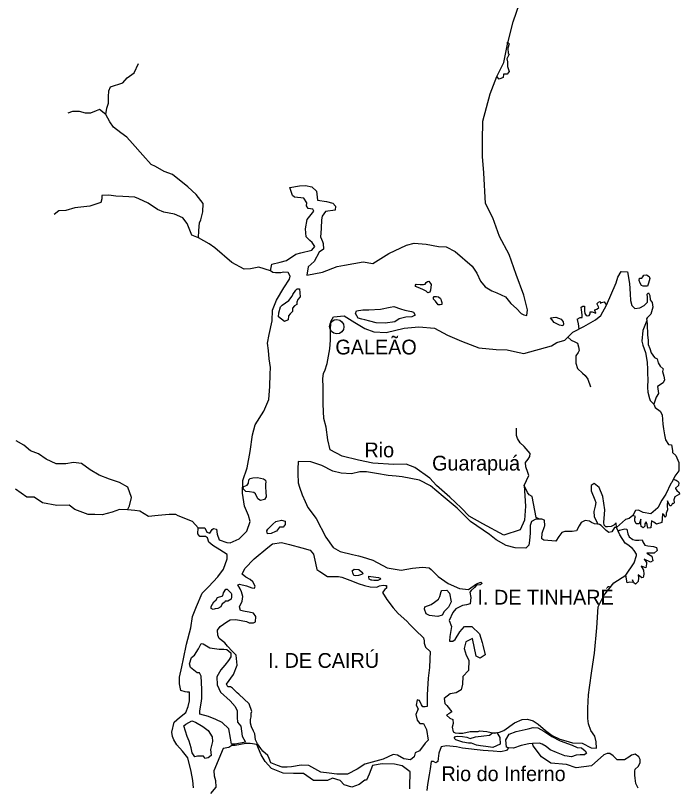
# Model space of a CAD drawing. Extents: x 662444 to 1640468, y 7452018 to 9606170.
# Drawn here: x 1132606 to 1162596, y 8490043 to 8524923 of the extents above; entities that cross this region are included whole.
import ezdxf

# ---------------------------------------------------------------- set-up
doc = ezdxf.new("R2010")
doc.units = 0
for name, color, linetype in [('Level 1', 7, 'Continuous'), ('Level 2', 7, 'Continuous'), ('Level 3', 7, 'Continuous')]:
    doc.layers.add(name, color=color, linetype=linetype)

msp = doc.modelspace()

# ---------------------------------------------------------------- linework, layer by layer
at = {"layer": 'Level 1'}
for points in [[(1153711, 8520144), (1154046, 8521381), (1154349, 8522164), (1154658, 8522801), (1154831, 8523631), (1155084, 8524637), (1155365, 8525464)], [(1154831, 8523631), (1154833, 8523709), (1154896, 8523641), (1154848, 8523442), (1154853, 8523208), (1154896, 8523173), (1154793, 8522965), (1154822, 8522830), (1154831, 8522730), (1154828, 8522619), (1154899, 8522395), (1154809, 8522275), (1154645, 8522268), (1154631, 8522123), (1154454, 8522039), (1154349, 8522164)], [(1136687, 8520441), (1136737, 8520729), (1136808, 8520961), (1136815, 8521239), (1136821, 8521517), (1136902, 8521693), (1137450, 8521880), (1137652, 8522097), (1137973, 8522334), (1138168, 8522752)], [(1140877, 8514871), (1140885, 8515205), (1140915, 8515549), (1140972, 8515692), (1141068, 8516057), (1141077, 8516423), (1140771, 8516831), (1140387, 8517174), (1139693, 8517735), (1139326, 8517877), (1138929, 8518098), (1138735, 8518191), (1138364, 8518612), (1137897, 8519134), (1137632, 8519418), (1137364, 8519625), (1137033, 8519877), (1136875, 8520114), (1136687, 8520441), (1136398, 8520670), (1136256, 8520618), (1135992, 8520513), (1135763, 8520508), (1135503, 8520580), (1135188, 8520588), (1134968, 8520504)], [(1143308, 8505974), (1143438, 8506426), (1143824, 8507051), (1144043, 8507579), (1144090, 8508167), (1144114, 8508712), (1144122, 8509023), (1144066, 8509413), (1144031, 8509792), (1143985, 8510116), (1144070, 8510503), (1144205, 8511133), (1144217, 8511611), (1144402, 8512063), (1144731, 8512622), (1144980, 8513016), (1145015, 8513138), (1144922, 8513307), (1144715, 8513323), (1144584, 8513293), (1144344, 8513298), (1144225, 8513312), (1144129, 8513381), (1144190, 8513680), (1144563, 8513771), (1144848, 8513853), (1145268, 8514143), (1145498, 8514205), (1145991, 8514315), (1146126, 8514478), (1146000, 8514671), (1145893, 8514751), (1145734, 8514922), (1145710, 8515289), (1145774, 8515710), (1146077, 8516081), (1146036, 8516171), (1145830, 8516209), (1145745, 8516322), (1145770, 8516455), (1145634, 8516670), (1145200, 8516714), (1145114, 8516793), (1145003, 8517152), (1145430, 8517220), (1145702, 8517235), (1145984, 8517173), (1146197, 8516979), (1146252, 8516577), (1146654, 8516512), (1146946, 8516438), (1147052, 8516302), (1147047, 8516124), (1146610, 8516068), (1146464, 8515860), (1146427, 8515683), (1146407, 8515306), (1146402, 8515083), (1146387, 8514928), (1146469, 8514715), (1146499, 8514614), (1146515, 8514358), (1146316, 8514229), (1146099, 8513812), (1145831, 8513563), (1145768, 8513186), (1146479, 8513325), (1147128, 8513587), (1147466, 8513645), (1148308, 8513792), (1148742, 8513715), (1149472, 8514164), (1150265, 8514545), (1150604, 8514637), (1151148, 8514590), (1151712, 8514488), (1152059, 8514468), (1152468, 8514258), (1153225, 8513595), (1153435, 8513278), (1153600, 8512918), (1153812, 8512657), (1154123, 8512483), (1154350, 8512388), (1154737, 8512212), (1154981, 8511917), (1155236, 8511688), (1155449, 8511460), (1155567, 8511391), (1155697, 8511365), (1155736, 8511631), (1155567, 8512281), (1155219, 8513223), (1154904, 8514121), (1154467, 8514943), (1154160, 8515774), (1153828, 8516427), (1153753, 8517819), (1153694, 8518554), (1153701, 8519255), (1153711, 8520144)], [(1144129, 8513381), (1143599, 8513550), (1143227, 8513470), (1142933, 8513455), (1142385, 8513768), (1141617, 8514420), (1141349, 8514604), (1140877, 8514871), (1140564, 8515001), (1140359, 8515529), (1140169, 8515778), (1139792, 8515943), (1139304, 8516043), (1139024, 8516150), (1138606, 8516449), (1138175, 8516637), (1138003, 8516708), (1137459, 8516743), (1137133, 8516762), (1136829, 8516802), (1136513, 8516788), (1136509, 8516632), (1136462, 8516466), (1135968, 8516311), (1135281, 8516239), (1134875, 8516115), (1134570, 8516100), (1134348, 8515938)], [(1156265, 8502165), (1156125, 8502235), (1155942, 8503196), (1155802, 8503266), (1155729, 8503379), (1155584, 8503694), (1155637, 8502759), (1155600, 8502115), (1155393, 8501686), (1154658, 8501437), (1153713, 8501950), (1153101, 8502299), (1152729, 8502675), (1152218, 8503154), (1151622, 8503692), (1151314, 8504022), (1150640, 8504494), (1150252, 8504659), (1149697, 8504640), (1148751, 8504696), (1148091, 8504834), (1147366, 8505019), (1146818, 8505299), (1146709, 8505758), (1146636, 8506327), (1146537, 8506718), (1146509, 8507364), (1146495, 8508131), (1146482, 8508510), (1146510, 8508765), (1146578, 8508863), (1146684, 8509194), (1146798, 8509859), (1146829, 8510258), (1146839, 8510647), (1146849, 8511092), (1146974, 8511311), (1147444, 8511355), (1147937, 8511054), (1148377, 8510788), (1148787, 8510633), (1149341, 8510598), (1150163, 8510789), (1150817, 8510851), (1151524, 8510800), (1152115, 8510486), (1152750, 8510214), (1153527, 8509906), (1154320, 8509831), (1154809, 8509819), (1155145, 8509744), (1155567, 8509645), (1156817, 8509992), (1157060, 8510153), (1157422, 8510255), (1157769, 8510614), (1158276, 8510868), (1158806, 8511167), (1159039, 8511361), (1159301, 8511833), (1159729, 8512846), (1159812, 8513099), (1159960, 8513351), (1160242, 8513333), (1160338, 8512819), (1160370, 8512340), (1160385, 8512051), (1160434, 8511827), (1160572, 8511679), (1160801, 8511707), (1161000, 8511813), (1161145, 8511976), (1161148, 8512076), (1161151, 8512199), (1161132, 8512333), (1161188, 8512387), (1161261, 8512274), (1161267, 8512073), (1161362, 8511949), (1161390, 8511748), (1161295, 8511428), (1161128, 8511265), (1161104, 8511210), (1161114, 8511143), (1161123, 8511098), (1161132, 8510987), (1161152, 8510486), (1161179, 8510252), (1161174, 8510051), (1161256, 8509871), (1161317, 8509681), (1161464, 8509477), (1161582, 8509407), (1161632, 8509228), (1161727, 8509081), (1161854, 8508956), (1161830, 8508834), (1161879, 8508633), (1161918, 8508465), (1161850, 8508322), (1161595, 8508161)], [(1161199, 8512831), (1161152, 8512688), (1160945, 8512693), (1160881, 8512728), (1160818, 8512830), (1160777, 8512953), (1160780, 8513053), (1160899, 8513050), (1160934, 8513116), (1160990, 8513193), (1161099, 8513201), (1161217, 8513131), (1161248, 8513042), (1161199, 8512831)], [(1145103, 8512246), (1145137, 8512312), (1145272, 8512509), (1145328, 8512574), (1145437, 8512571), (1145455, 8512393), (1145461, 8512215), (1145360, 8512095), (1145314, 8511963), (1145311, 8511863), (1145212, 8511810), (1145122, 8511701), (1145119, 8511556), (1145018, 8511436), (1144940, 8511360), (1144914, 8511172), (1144749, 8511098), (1144492, 8511304), (1144497, 8511482), (1144579, 8511758), (1144647, 8511834), (1144945, 8512038), (1145103, 8512246)], [(1151348, 8512517), (1151324, 8512429), (1151236, 8512397), (1151151, 8512466), (1151000, 8512537), (1150795, 8512631), (1150677, 8512678), (1150667, 8512745), (1150701, 8512789), (1150875, 8512773), (1151038, 8512769), (1151104, 8512779), (1151160, 8512866), (1151216, 8512910), (1151281, 8512919), (1151376, 8512772), (1151348, 8512517)], [(1151575, 8512011), (1151490, 8512113), (1151481, 8512180), (1151515, 8512224), (1151613, 8512233), (1151710, 8512208), (1151796, 8512139), (1151817, 8512105), (1151837, 8512049), (1151857, 8511960), (1151854, 8511860), (1151789, 8511850), (1151702, 8511852), (1151575, 8512011)], [(1158068, 8510764), (1158028, 8510986), (1157990, 8511187), (1157979, 8511209), (1158101, 8511284), (1158199, 8511271), (1158191, 8511404), (1158175, 8511627), (1158156, 8511750), (1158233, 8511792), (1158299, 8511791), (1158304, 8511557), (1158312, 8511457), (1158386, 8511366), (1158451, 8511353), (1158517, 8511374), (1158562, 8511440), (1158564, 8511528), (1158652, 8511537), (1158813, 8511478), (1158773, 8511601), (1158806, 8511634), (1158861, 8511655), (1158950, 8511730), (1158878, 8511877), (1158868, 8511910), (1158935, 8511975), (1159011, 8511996), (1159031, 8511906), (1159065, 8511961), (1159185, 8511991), (1159301, 8511833)], [(1149522, 8511750), (1149686, 8511779), (1149988, 8511672), (1150183, 8511611), (1150334, 8511574), (1150497, 8511548), (1150583, 8511513), (1150656, 8511377), (1150513, 8511314), (1150229, 8511299), (1149933, 8511217), (1149734, 8511077), (1149308, 8511021), (1148895, 8511042), (1148614, 8511116), (1148386, 8511166), (1148246, 8511202), (1148083, 8511251), (1147958, 8511465), (1148005, 8511586), (1148288, 8511624), (1148571, 8511617), (1149084, 8511660), (1149522, 8511750)], [(1156930, 8511057), (1156824, 8511182), (1156772, 8511261), (1157012, 8511289), (1157250, 8511205), (1157334, 8511081), (1157353, 8510980), (1157329, 8510903), (1157167, 8510929), (1156930, 8511057)], [(1161114, 8511143), (1160939, 8510691), (1160895, 8510214), (1160944, 8510024), (1161056, 8509698), (1161132, 8509263), (1161146, 8508929), (1161152, 8508740), (1161157, 8508495), (1161148, 8508117), (1161164, 8507905), (1161244, 8507614), (1161264, 8507524), (1161434, 8507365)], [(1157535, 8510397), (1157694, 8510249), (1157867, 8510178), (1157985, 8510119), (1158035, 8509951), (1158064, 8509784), (1158018, 8509696), (1157916, 8509542), (1157919, 8509220), (1157990, 8508973), (1158213, 8508757), (1158330, 8508654), (1158457, 8508495), (1158568, 8508147)], [(1161595, 8508161), (1161652, 8507837), (1161539, 8507673), (1161434, 8507365), (1161495, 8507207), (1161720, 8507046), (1161814, 8506888), (1161836, 8506454), (1161864, 8506253), (1161911, 8505973), (1161960, 8505750), (1162096, 8505546), (1162237, 8505520), (1162275, 8505275), (1162272, 8505186), (1162432, 8505048), (1162566, 8504723), (1162567, 8504344), (1162376, 8504116), (1162249, 8503818), (1162205, 8503775), (1161975, 8503302), (1161794, 8503018), (1161622, 8502677), (1161300, 8502407), (1160953, 8502471), (1160749, 8502577), (1160607, 8502558), (1160482, 8502339), (1160326, 8502198), (1160161, 8502157), (1159750, 8501790)], [(1140647, 8490027), (1140612, 8490361), (1140545, 8490763), (1140397, 8491389), (1140144, 8491685), (1139900, 8491968), (1139754, 8492205), (1139692, 8492352), (1139675, 8492541), (1139773, 8492994), (1140017, 8493200), (1140306, 8493437), (1140399, 8493702), (1140460, 8493967), (1140467, 8494245), (1140469, 8494345), (1140361, 8494359), (1140263, 8494361), (1140079, 8494421), (1140021, 8494723), (1140018, 8495034), (1140116, 8495499), (1140190, 8495853), (1140337, 8496517), (1140529, 8497257), (1140596, 8497767), (1140781, 8498218), (1141035, 8498823), (1141325, 8499117), (1141749, 8499562), (1142008, 8499912), (1142160, 8500375), (1142165, 8500564), (1141833, 8500783), (1141522, 8500980), (1141341, 8501129), (1141280, 8501319), (1141183, 8501377), (1141086, 8501380), (1141031, 8501381), (1140933, 8501383), (1140849, 8501508), (1140856, 8501774), (1141051, 8501769), (1141160, 8501778), (1141243, 8501587), (1141383, 8501528), (1141496, 8501703), (1141551, 8501746), (1141681, 8501721), (1141719, 8501487), (1141811, 8501229), (1142145, 8501109), (1142309, 8501105), (1142715, 8501284), (1142894, 8501458), (1143061, 8501632), (1143202, 8502062), (1143133, 8502331), (1142947, 8502747), (1142863, 8503349), (1142877, 8503916), (1143065, 8504489), (1143213, 8505220), (1143308, 8505974)], [(1155584, 8503694), (1155791, 8504134), (1155740, 8504280), (1155659, 8504538), (1155642, 8504727), (1155755, 8504880), (1155834, 8505001), (1155848, 8505134), (1155573, 8505452), (1155392, 8505612), (1155277, 8505815), (1155226, 8505950), (1155234, 8506283)], [(1137665, 8502596), (1137757, 8502772), (1137853, 8503147), (1137679, 8503607), (1137303, 8503828), (1136850, 8503972), (1136386, 8504150), (1135978, 8504393), (1135583, 8504680), (1135225, 8504733), (1134886, 8504664), (1134440, 8504674), (1133988, 8504874), (1133645, 8505116), (1133290, 8505258), (1132991, 8505509), (1132636, 8505707)], [(1150075, 8504074), (1149804, 8504114), (1149434, 8504134), (1148914, 8504225), (1148459, 8504303), (1148306, 8504307), (1148154, 8504299), (1147782, 8504219), (1147314, 8504242), (1146936, 8504340), (1146441, 8504585), (1145945, 8504753), (1145368, 8504778), (1145360, 8504423), (1145355, 8504234), (1145378, 8503811), (1145438, 8503620), (1145560, 8503261), (1145694, 8502958), (1145808, 8502699), (1146187, 8502201), (1146624, 8501356), (1146950, 8500892), (1147272, 8500707), (1147824, 8500571), (1148094, 8500509), (1148256, 8500471), (1148742, 8500315), (1149398, 8499965), (1150026, 8499861), (1150529, 8499949), (1150987, 8499993), (1151291, 8499963), (1151376, 8499894), (1151695, 8499575), (1152144, 8499264), (1152661, 8499029), (1153063, 8498986), (1153428, 8499243), (1153626, 8499316), (1153679, 8499260), (1153590, 8499206), (1153427, 8499188), (1153337, 8499079), (1153192, 8498938), (1153125, 8498862), (1153163, 8498627), (1153134, 8498339), (1152970, 8498298), (1152795, 8498269), (1152486, 8498110), (1152351, 8497947), (1152190, 8497595), (1152303, 8497325), (1152216, 8496871), (1152211, 8496660), (1152352, 8496657), (1152463, 8496732), (1152678, 8497082), (1152891, 8497322), (1153217, 8497314), (1153568, 8496982), (1153689, 8496601), (1153719, 8496478), (1153817, 8496042), (1153596, 8495892), (1153413, 8495985), (1153248, 8496779), (1152939, 8496620), (1152866, 8496321), (1152957, 8496030), (1153082, 8495804), (1153059, 8495327), (1152802, 8495055), (1152794, 8494711), (1152733, 8494456), (1152502, 8494329), (1152239, 8494279), (1151973, 8494064), (1152000, 8493841), (1152021, 8493807), (1152085, 8493749), (1152317, 8493466), (1152184, 8493369), (1152074, 8493316), (1152223, 8493179), (1152352, 8493120), (1152369, 8492931), (1152321, 8492765), (1152371, 8492564), (1152457, 8492517), (1152631, 8492502), (1152815, 8492497), (1153133, 8492578), (1153503, 8492580), (1153569, 8492601), (1153894, 8492570), (1154219, 8492507), (1154459, 8492545), (1154668, 8492618), (1155144, 8492962)], [(1143804, 8503993), (1143901, 8503936), (1143920, 8503835), (1143897, 8503769), (1143894, 8503680), (1143893, 8503613), (1143920, 8503401), (1143926, 8503179), (1143858, 8503058), (1143671, 8503007), (1143554, 8503088), (1143439, 8503313), (1143375, 8503370), (1143180, 8503408), (1143006, 8503412), (1142900, 8503515), (1142891, 8503604), (1142925, 8503637), (1143068, 8503700), (1143135, 8503798), (1143150, 8503943), (1143206, 8503997), (1143326, 8504038), (1143544, 8504055), (1143804, 8503993)], [(1155144, 8492962), (1155486, 8493120), (1155736, 8493136), (1155985, 8493063), (1156210, 8492913), (1156539, 8492616), (1156850, 8492397), (1157182, 8492222), (1157453, 8492148), (1157755, 8492063), (1158201, 8492041), (1158598, 8491830), (1158848, 8491824), (1158833, 8492103), (1158775, 8492360), (1158585, 8492620), (1158484, 8492923), (1158457, 8493169), (1158458, 8493625), (1158484, 8494225), (1158525, 8494557), (1158631, 8495322), (1158748, 8496109), (1158853, 8497252), (1158920, 8498207), (1159183, 8498723), (1159633, 8499290), (1160175, 8499632), (1160548, 8500190), (1160654, 8500521), (1160656, 8500588), (1160551, 8500746), (1160466, 8500837), (1160253, 8501010), (1160145, 8501079), (1159904, 8501452), (1159750, 8501790), (1159662, 8501792), (1159538, 8501595), (1159396, 8501565), (1159278, 8501657), (1159204, 8501725), (1159055, 8501874), (1158984, 8501929), (1158904, 8501944), (1158752, 8501959), (1158612, 8502018), (1158527, 8502076), (1158332, 8502114), (1158155, 8502018), (1158064, 8501865), (1157939, 8501645), (1157753, 8501617), (1157416, 8501603), (1157273, 8501562), (1157149, 8501387), (1157002, 8501179), (1156470, 8501215), (1156384, 8501272), (1156391, 8501539), (1156496, 8501837), (1156519, 8501870), (1156492, 8502115), (1156384, 8502162), (1156265, 8502165), (1156112, 8502169), (1155903, 8502063), (1155844, 8501886), (1155857, 8501541), (1155827, 8501197), (1155790, 8500998), (1155656, 8500857), (1155177, 8500869), (1154766, 8500979), (1154315, 8501235), (1154016, 8501475), (1153160, 8502064), (1152554, 8502657), (1151925, 8503195), (1151350, 8503676), (1150855, 8503922), (1150075, 8504074)], [(1162308, 8503973), (1162437, 8503936), (1162534, 8503867), (1162565, 8503811), (1162551, 8503689), (1162417, 8503570), (1162417, 8503547), (1162480, 8503457), (1162575, 8503365), (1162596, 8503298), (1162386, 8503181), (1162339, 8503038), (1162357, 8502904), (1162313, 8502860), (1162270, 8502884), (1162212, 8502763), (1162158, 8502775), (1162044, 8503000), (1162038, 8502767), (1162055, 8502589), (1161997, 8502445), (1161995, 8502334), (1161949, 8502235), (1161887, 8502381), (1161822, 8502405), (1161806, 8502183), (1161802, 8502017), (1161549, 8501934), (1161432, 8502037), (1161335, 8502095), (1161321, 8501940), (1161295, 8501773), (1161164, 8501754), (1161144, 8501822), (1161135, 8501922), (1161084, 8502046), (1161027, 8501958), (1161025, 8501858), (1160947, 8501782), (1160861, 8501840), (1160853, 8501962), (1160848, 8502174), (1160766, 8501953), (1160635, 8501957), (1160573, 8502092), (1160576, 8502214), (1160600, 8502291), (1160482, 8502339)], [(1140856, 8501774), (1140602, 8502069), (1139955, 8502319), (1139847, 8502377), (1139543, 8502373), (1139052, 8502340), (1138616, 8502295), (1138230, 8502527), (1138002, 8502566), (1137665, 8502596), (1137307, 8502605), (1136967, 8502490), (1136517, 8502357), (1136191, 8502376), (1135886, 8502372), (1135294, 8502608), (1135026, 8502793), (1134471, 8502784), (1133832, 8502910), (1133446, 8503164), (1133120, 8503161), (1132606, 8503517)], [(1159750, 8501790), (1159733, 8502001), (1159632, 8501893), (1159511, 8501840), (1159348, 8501822), (1159261, 8501824), (1159197, 8501892), (1159178, 8502015), (1159209, 8502392), (1159214, 8502593), (1159131, 8503184), (1158967, 8503600), (1158743, 8503772), (1158610, 8503686), (1158604, 8503453), (1158768, 8503037), (1158820, 8502925), (1158783, 8502759), (1158723, 8502516), (1158739, 8502293), (1158904, 8501944)], [(1144222, 8501937), (1144366, 8502056), (1144618, 8502117), (1144781, 8502079), (1144788, 8501924), (1144698, 8501803), (1144524, 8501808), (1144389, 8501622), (1144356, 8501612), (1144157, 8501516), (1143994, 8501498), (1143954, 8501633), (1144010, 8501720), (1144222, 8501937)], [(1159811, 8501632), (1159877, 8501675), (1160129, 8501736), (1160216, 8501722), (1160265, 8501499), (1160316, 8501364), (1160487, 8501248), (1160606, 8501212), (1160759, 8501219), (1160901, 8501238), (1160942, 8501137), (1161025, 8500990), (1161166, 8500965), (1161426, 8500925), (1161556, 8500888), (1161585, 8500754), (1161452, 8500635), (1161125, 8500632), (1161339, 8500493), (1161389, 8500292), (1161278, 8500228), (1160998, 8500357), (1161103, 8500210), (1161102, 8500143), (1161076, 8499966), (1160860, 8500049), (1160964, 8499869), (1160981, 8499679), (1160945, 8499535), (1160890, 8499514), (1160730, 8499652), (1160738, 8499518), (1160734, 8499352), (1160600, 8499232), (1160536, 8499290), (1160474, 8499425), (1160482, 8499313), (1160352, 8499317), (1160231, 8499286), (1160175, 8499632)], [(1142748, 8499027), (1142643, 8499207), (1142731, 8499238), (1143034, 8499153), (1143282, 8499069), (1143401, 8499044), (1143436, 8499143), (1143321, 8499335), (1143204, 8499438), (1143011, 8499554), (1142840, 8499680), (1142966, 8499933), (1143379, 8500368), (1144001, 8500886), (1144212, 8501059), (1144627, 8501116), (1144983, 8501018), (1145535, 8500871), (1145913, 8500773), (1146072, 8500591), (1146149, 8500178), (1146218, 8499898), (1146358, 8499806), (1146700, 8499575), (1146929, 8499570), (1147190, 8499574), (1147342, 8499549), (1147827, 8499370), (1148085, 8499263), (1148366, 8499168), (1148626, 8499106), (1148919, 8499099), (1149040, 8499151), (1149215, 8499180), (1149302, 8499178), (1149367, 8499176), (1149364, 8499054), (1149287, 8498989), (1149185, 8498847), (1149384, 8498542), (1149669, 8498157), (1149891, 8497907), (1150285, 8497564), (1150412, 8497405), (1150763, 8497063), (1150943, 8496891), (1151039, 8496800), (1151058, 8496677), (1151066, 8496566), (1151127, 8496386), (1151329, 8496192), (1151320, 8495848), (1151311, 8495470), (1151245, 8494982), (1151211, 8494483), (1151205, 8494238), (1151194, 8493827), (1151191, 8493705), (1151104, 8493685), (1151006, 8493687), (1150943, 8493778), (1150850, 8493969), (1150742, 8494005), (1150703, 8493761), (1150797, 8493603), (1150682, 8493350), (1150741, 8493093), (1150868, 8492934), (1150944, 8492932), (1151031, 8492930), (1151166, 8492671), (1151241, 8492191), (1151107, 8492050), (1150848, 8491700), (1150650, 8491605), (1150613, 8491428), (1150446, 8491288), (1150143, 8491340), (1149864, 8491502), (1149658, 8491530), (1149218, 8491329), (1148386, 8491105), (1148032, 8490869), (1147602, 8490646), (1147113, 8490647), (1146766, 8490700), (1146397, 8490731), (1145849, 8491034), (1145513, 8491053), (1145076, 8490975), (1144869, 8490969), (1144651, 8490963), (1144446, 8491046), (1144134, 8491154), (1144062, 8491356), (1144000, 8491491), (1143777, 8491685), (1143682, 8491810), (1143535, 8492025), (1143452, 8492193), (1143415, 8492472)], [(1148111, 8499886), (1148229, 8499794), (1148261, 8499771), (1148292, 8499703), (1148226, 8499660), (1148193, 8499650), (1148105, 8499619), (1147942, 8499612), (1147887, 8499624), (1147836, 8499748), (1147827, 8499804), (1147806, 8499837), (1147895, 8499913), (1148111, 8499886)], [(1149006, 8499530), (1149071, 8499506), (1149091, 8499450), (1148970, 8499397), (1148850, 8499400), (1148785, 8499402), (1148698, 8499404), (1148666, 8499405), (1148580, 8499463), (1148560, 8499552), (1148561, 8499585), (1148648, 8499583), (1149006, 8499530)], [(1141669, 8498519), (1141726, 8498629), (1141967, 8498701), (1142003, 8498833), (1142105, 8498998), (1142171, 8499007), (1142351, 8498825), (1142361, 8498791), (1142358, 8498647), (1142344, 8498547), (1142201, 8498462), (1142070, 8498465), (1142058, 8498421), (1141948, 8498345), (1141879, 8498214), (1141747, 8498139), (1141627, 8498109), (1141528, 8498089), (1141442, 8498135), (1141444, 8498224), (1141569, 8498432), (1141669, 8498519)], [(1143415, 8492472), (1143353, 8492596), (1143260, 8492787), (1143220, 8492944), (1143224, 8493111), (1143249, 8493232), (1143253, 8493399), (1143287, 8493476), (1143165, 8493824), (1142687, 8494269), (1142612, 8494315), (1142495, 8494440), (1142410, 8494532), (1142324, 8494589), (1142194, 8494592), (1142132, 8494716), (1142458, 8495153), (1142620, 8495572), (1142566, 8496029), (1142386, 8496211), (1142184, 8496427), (1142068, 8496586), (1141801, 8496781), (1141739, 8496927), (1141734, 8497150), (1141858, 8497314), (1142157, 8497529), (1142300, 8497614), (1142562, 8497641), (1143038, 8497541), (1143167, 8497482), (1143352, 8497477), (1143440, 8497531), (1143468, 8497764), (1143352, 8497922), (1143157, 8497971), (1142984, 8497998), (1142767, 8498036), (1142717, 8498204), (1142843, 8498468), (1142881, 8498668), (1142810, 8498880), (1142748, 8499027)], [(1151536, 8498412), (1151713, 8498552), (1151771, 8498673), (1151831, 8498905), (1151854, 8498938), (1152083, 8498965), (1152210, 8498829), (1152276, 8498427), (1152161, 8498185), (1151961, 8498001), (1151881, 8497836), (1151673, 8497774), (1151542, 8497789), (1151304, 8497817), (1151153, 8497887), (1151071, 8498100), (1151095, 8498200), (1151381, 8498315), (1151536, 8498412)], [(1142369, 8492004), (1142323, 8492276), (1142246, 8492690), (1141937, 8492975), (1141658, 8493115), (1141324, 8493246), (1140935, 8493355), (1140928, 8493511), (1140990, 8493854), (1141017, 8494065), (1141016, 8494465), (1141002, 8494788), (1140987, 8495078), (1140915, 8495224), (1140806, 8495226), (1140518, 8495467), (1140468, 8495635), (1140562, 8495911), (1140695, 8496030), (1140876, 8496314), (1140991, 8496556), (1141088, 8496532), (1141388, 8496358), (1141811, 8496292), (1142018, 8496298), (1142148, 8496284)], [(1142148, 8496284), (1142329, 8496135), (1142336, 8495945), (1142234, 8495781), (1142055, 8495574), (1141886, 8495356), (1141694, 8495038), (1141718, 8494682), (1141862, 8494356), (1142309, 8493967), (1142531, 8493706), (1142624, 8493503), (1142617, 8493214), (1142634, 8493003), (1142782, 8492810), (1142847, 8492364), (1143002, 8492100)], [(1141309, 8492624), (1141486, 8492330), (1141503, 8492119), (1141455, 8491942), (1141418, 8491765), (1141444, 8491497), (1141311, 8491378), (1141158, 8491360), (1141137, 8491394), (1141095, 8491461), (1140943, 8491465), (1140834, 8491457), (1140703, 8491437), (1140588, 8491618), (1140539, 8491831), (1140448, 8492144), (1140366, 8492346), (1140204, 8492828), (1140293, 8492904), (1140568, 8493053), (1140741, 8493004), (1141063, 8492807), (1141309, 8492624)], [(1154877, 8491834), (1154780, 8491870), (1154755, 8492193), (1154903, 8492456), (1155222, 8492582), (1155758, 8492691), (1155988, 8492752), (1156190, 8492741), (1156467, 8492591), (1156826, 8492350), (1157204, 8492158), (1157752, 8491952), (1157968, 8491857), (1158174, 8491830), (1158334, 8491704), (1158396, 8491591), (1158307, 8491515), (1158112, 8491520), (1157926, 8491502), (1157718, 8491430), (1157414, 8491482), (1157037, 8491625), (1156757, 8491754), (1156565, 8491892), (1156393, 8491997), (1156264, 8492044), (1155959, 8492030)], [(1153759, 8492385), (1154010, 8492412), (1154154, 8492508), (1154339, 8492526), (1154486, 8492311), (1154489, 8492000), (1154159, 8491852), (1153845, 8491904), (1153606, 8491921), (1153433, 8491959), (1153196, 8492043), (1153065, 8492046), (1152816, 8492097), (1152633, 8492146), (1152492, 8492194), (1152418, 8492273), (1152485, 8492349), (1152583, 8492358), (1152801, 8492342), (1152985, 8492315), (1153147, 8492266), (1153388, 8492338), (1153759, 8492385)], [(1143002, 8492100), (1142521, 8492001), (1142369, 8492004)], [(1143013, 8492037), (1142532, 8491938), (1142380, 8491942)], [(1150414, 8489987), (1150421, 8490265), (1150428, 8490554), (1150433, 8490754), (1150070, 8491019), (1149724, 8491105), (1149169, 8491108), (1148732, 8491041), (1148581, 8490644), (1148455, 8490381), (1148389, 8490371), (1148135, 8490188), (1147794, 8490063), (1147449, 8490172), (1147269, 8490354), (1146923, 8490463), (1146692, 8490368), (1146061, 8490361), (1145612, 8490673), (1145155, 8490684), (1144699, 8490695), (1144171, 8490897), (1143885, 8491215), (1143697, 8491520), (1143501, 8491981), (1143209, 8492032), (1143013, 8492037)], [(1160729, 8490009), (1160625, 8490223), (1160588, 8490468), (1160569, 8490602), (1160574, 8490780), (1160587, 8490869), (1160721, 8490988), (1160823, 8491152), (1160816, 8491308), (1160764, 8491431), (1160593, 8491558), (1160429, 8491507), (1160307, 8491410), (1160108, 8491292), (1159782, 8491300), (1159601, 8491483), (1159452, 8491587), (1159332, 8491579), (1159178, 8491527), (1158621, 8491018), (1157923, 8490935), (1157492, 8491091), (1156786, 8491142), (1156368, 8491430), (1155989, 8491929), (1155959, 8492030), (1155785, 8492023), (1155445, 8491942), (1155094, 8491829), (1154877, 8491834), (1154787, 8491714), (1154524, 8491654), (1154177, 8491685), (1153732, 8491718), (1152799, 8491819), (1152517, 8491882), (1152072, 8491926), (1151832, 8491876), (1151727, 8491601), (1151699, 8491357), (1151685, 8491224), (1151586, 8491160), (1151489, 8491218), (1151380, 8491220), (1151329, 8490888), (1151289, 8490611), (1151213, 8490179), (1151185, 8489913)], [(1142380, 8491942), (1142247, 8491845), (1141985, 8491807), (1141558, 8490794), (1141585, 8490571), (1141645, 8490358), (1141649, 8490058), (1141413, 8489775)]]:
    msp.add_lwpolyline(points, dxfattribs=at)
at = {"layer": 'Level 2'}
msp.add_ellipse((1147116, 8510863), major_axis=(326, -8), ratio=0.999997, dxfattribs=at)

# ---------------------------------------------------------------- texts
at = {"layer": 'Level 3'}
for s, height, p in [('GALEÃO', 668, (1147053, 8509608)), ('Rio ', 667.9, (1148366, 8504961)), ('Guarapuá', 667.9, (1151421, 8504364)), ('I. DE TINHARÉ', 667.79, (1153470, 8498308)), ('I. DE CAIRÚ', 667.6, (1144015, 8495451)), ('Rio do Inferno', 667.6, (1151844, 8490334))]:
    msp.add_text(s, height=height, dxfattribs=at).set_placement(p)

doc.saveas('drawing.dxf')
